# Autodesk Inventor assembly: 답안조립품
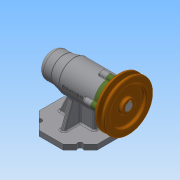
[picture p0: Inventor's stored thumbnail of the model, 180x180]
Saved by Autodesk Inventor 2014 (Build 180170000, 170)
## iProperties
Created: 2019-12
Part Number: 답안조립품
Document SubType Name: Assembly
Designer: net
Author: net
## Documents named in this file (12)
- C:\Users\net\Desktop\491204V1039\답안조립품.iam
- C:\Users\net\Desktop\491204V1039\답안도면.ipt
- C:\Users\net\Desktop\491204V1039\베어링 51202.ipt
- C:\Users\net\Desktop\491204V1039\베어링 6004.ipt
- C:\Users\net\Desktop\491204V1039\어댑터슬리브.ipt
- C:\Users\net\Desktop\491204V1039\볼트 M4.ipt
- C:\Users\net\Desktop\491204V1039\축.ipt
- C:\Users\net\Desktop\491204V1039\키 5 x 5 x 16.ipt
- C:\Users\net\Desktop\491204V1039\멈춤나사 M3.ipt
- C:\Users\net\Desktop\491204V1039\커버.ipt
- C:\Users\net\Desktop\491204V1039\오일 실.ipt
- C:\Users\net\Desktop\491204V1039\V벨트풀리.ipt
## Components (1 placed, 1 different names)
1. V벨트풀리:1
